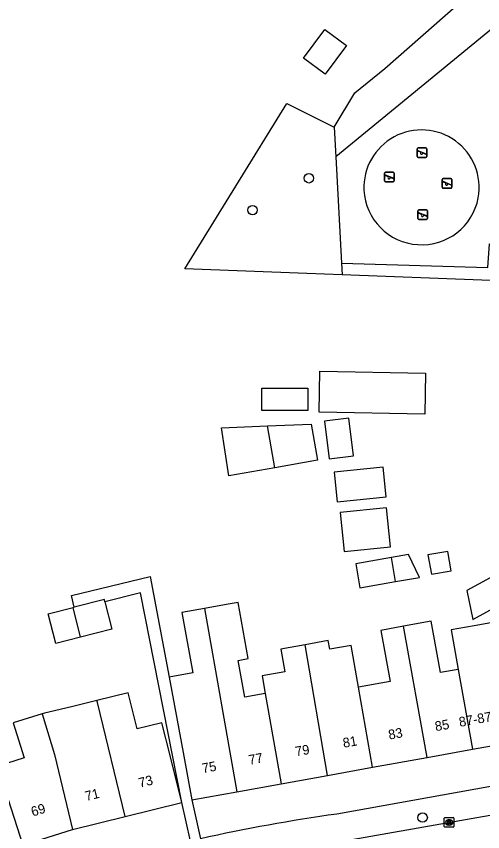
# Model space of a CAD drawing. Extents: x 160158 to 160921, y 381517 to 382041.
# Drawn here: x 160425.2 to 160473.6, y 381721.4 to 381806 of the extents above; entities that cross this region are included whole.
import ezdxf

# ---------------------------------------------------------------- set-up
doc = ezdxf.new("R2010")
doc.units = 0
for name, color, linetype in [('IMGEO_Boom', 7, 'Continuous'), ('IMGEO_Groenvoorziening', 7, 'Continuous'), ('IMGEO_Kolk', 7, 'Continuous'), ('IMGEO_Pand', 7, 'Continuous'), ('IMGEO_Pand_nummerreeks', 7, 'Continuous'), ('IMGEO_Rijbaan_lokaal_open', 7, 'Continuous'), ('IMGEO_Speelvoorziening', 7, 'Continuous'), ('IMGEO_Voetpad_open', 7, 'Continuous')]:
    doc.layers.add(name, color=color, linetype=linetype)

msp = doc.modelspace()

# ---------------------------------------------------------------- linework, layer by layer
at = {"layer": 'IMGEO_Boom'}
for centre in [(160455.579, 381789.21), (160449.734, 381785.912), (160467.376, 381722.867)]:
    msp.add_circle(centre, 0.489, dxfattribs=at)
at = {"layer": 'IMGEO_Groenvoorziening'}
for points in [[(160458.209, 381794.524), (160460.339, 381798.072), (160463.455, 381800.599), (160473.68, 381809.649), (160478.409, 381814.815)], [(160482.021, 381811.85), (160479.918, 381809.167), (160458.371, 381791.432)], [(160459.011, 381779.182), (160455.366, 381779.322), (160442.688, 381779.806), (160453.283, 381796.984), (160458.209, 381794.524)], [(160458.209, 381794.524), (160458.371, 381791.432)], [(160458.371, 381791.432), (160458.948, 381780.395)], [(160458.948, 381780.395), (160474.146, 381779.946), (160474.316, 381782.426), (160495.817, 381780.983)], [(160458.948, 381780.395), (160459.011, 381779.182)], [(160495.695, 381777.781), (160473.521, 381778.628), (160459.011, 381779.182)]]:
    msp.add_lwpolyline(points, dxfattribs=at)
for centre, radius, start, end in [((160467.262, 381788.252), 5.98, 349.80072, 182.53906), ((160467.265, 381788.296), 5.985, 182.96158, 349.37821)]:
    msp.add_arc(centre, radius, start, end, dxfattribs=at)
at = {"layer": 'IMGEO_Kolk'}
for p, q in [((160469.619, 381721.936), (160469.619, 381722.788)), ((160469.694, 381722.862), (160470.546, 381722.862)), ((160470.107, 381722.642), (160470.132, 381722.642)), ((160470.62, 381722.788), (160470.62, 381721.936)), ((160470.546, 381721.862), (160469.694, 381721.862)), ((160470.13, 381722.082), (160470.105, 381722.082))]:
    msp.add_line(p, q, dxfattribs=at)
for points in [[(160469.619, 381721.936), (160469.619, 381722.788)], [(160469.694, 381722.862), (160470.546, 381722.862)], [(160469.94, 381722.562), (160470.063, 381722.562), (160470.063, 381722.411), (160470.193, 381722.562), (160470.357, 381722.562), (160470.211, 381722.411), (160470.364, 381722.162), (160470.212, 381722.162), (160470.127, 381722.326), (160470.063, 381722.259), (160470.063, 381722.162), (160469.94, 381722.162), (160469.94, 381722.562)], [(160470.62, 381722.788), (160470.62, 381721.936)], [(160470.546, 381721.862), (160469.694, 381721.862)]]:
    msp.add_lwpolyline(points, dxfattribs=at)
for centre, start, end in [((160469.696, 381722.786), 91.55205, 178.44795), ((160469.696, 381722.786), 91.55205, 178.44795), ((160470.544, 381722.786), 1.55205, 88.44795), ((160470.544, 381722.786), 1.55205, 88.44795), ((160469.696, 381721.938), 181.55205, 268.44795), ((160469.696, 381721.938), 181.55205, 268.44795), ((160470.544, 381721.938), 271.55205, 358.44795), ((160470.544, 381721.938), 271.55205, 358.44795)]:
    msp.add_arc(centre, 0.0765, start, end, dxfattribs=at)
for centre, major_axis, ratio, start_param, end_param in [((160470.106, 381722.362), (-0.387, 0.002), 0.722429, 4.712389, 7.853982), ((160470.131, 381722.362), (-0.39, 0.002), 0.717154, 1.570796, 4.712389)]:
    msp.add_ellipse(centre, major_axis=major_axis, ratio=ratio, start_param=start_param, end_param=end_param, dxfattribs=at)
at = {"layer": 'IMGEO_Pand'}
for points in [[(160457.222, 381804.671), (160459.482, 381802.99), (160457.263, 381800.007), (160455.003, 381801.688), (160457.222, 381804.671)], [(160456.723, 381769.193), (160467.67, 381768.98), (160467.586, 381764.727), (160456.639, 381764.941), (160456.723, 381769.193)], [(160450.684, 381767.436), (160455.461, 381767.436), (160455.461, 381765.129), (160450.684, 381765.129), (160450.684, 381767.436)], [(160451.296, 381763.518), (160455.802, 381763.698), (160456.483, 381759.963), (160452.039, 381759.176)], [(160457.689, 381760.087), (160460.216, 381760.409), (160459.717, 381764.331), (160457.19, 381764.009), (160457.689, 381760.087)], [(160452.039, 381759.176), (160447.279, 381758.333), (160446.516, 381763.327), (160451.296, 381763.518)], [(160452.039, 381759.176), (160451.296, 381763.518)], [(160458.49, 381755.634), (160463.575, 381756.136), (160463.27, 381759.227), (160458.185, 381758.725), (160458.49, 381755.634)], [(160459.219, 381750.492), (160464.026, 381750.966), (160463.627, 381755.014), (160458.82, 381754.539), (160459.219, 381750.492)], [(160464.575, 381747.357), (160467.04, 381747.792), (160465.923, 381750.166), (160464.135, 381749.85)], [(160468.284, 381748.111), (160470.334, 381748.481), (160469.973, 381750.485), (160467.923, 381750.115), (160468.284, 381748.111)], [(160464.135, 381749.85), (160460.437, 381749.198), (160460.876, 381746.705), (160464.575, 381747.357)], [(160464.575, 381747.357), (160464.135, 381749.85)], [(160471.969, 381746.44), (160472.579, 381743.425), (160476.938, 381745.793), (160474.382, 381747.751), (160471.969, 381746.44)], [(160434.412, 381745.253), (160434.351, 381745.492), (160431.229, 381744.692)], [(160434.412, 381745.253), (160435.139, 381742.423), (160431.894, 381741.59)], [(160451.034, 381735.746), (160448.923, 381735.366), (160448.236, 381739.18), (160449.275, 381739.367), (160448.226, 381745.193), (160447.187, 381745.006), (160444.726, 381744.563)], [(160431.894, 381741.59), (160429.304, 381740.925), (160428.516, 381743.995), (160431.106, 381744.66)], [(160431.106, 381744.66), (160431.229, 381744.692)], [(160431.894, 381741.59), (160431.106, 381744.66)], [(160444.726, 381744.563), (160442.398, 381744.144), (160443.525, 381737.883), (160441.064, 381737.44)], [(160444.726, 381744.563), (160448.085, 381725.541)], [(160465.393, 381742.715), (160463.042, 381742.292), (160464, 381736.971), (160460.725, 381736.382)], [(160471.074, 381738.24), (160469.223, 381737.907), (160468.265, 381743.232), (160465.393, 381742.715)], [(160467.851, 381729.099), (160465.393, 381742.715)], [(160475.027, 381743.189), (160474.825, 381743.153), (160472.71, 381742.772), (160470.335, 381742.344), (160471.074, 381738.24)], [(160460.725, 381736.382), (160459.961, 381740.724), (160457.747, 381740.334), (160457.585, 381741.234), (160455.186, 381740.802)], [(160455.186, 381740.802), (160452.655, 381740.346), (160453.081, 381737.983), (160450.714, 381737.568), (160451.034, 381735.746)], [(160457.509, 381727.237), (160455.186, 381740.802)], [(160471.074, 381738.24), (160472.561, 381729.947)], [(160441.064, 381737.44), (160441.896, 381732.975), (160442.536, 381729.622), (160443.422, 381724.701)], [(160442.382, 381724.436), (160441.175, 381729.289), (160440.325, 381732.707), (160437.753, 381732.067), (160436.82, 381735.818), (160433.583, 381735.013)], [(160462.186, 381728.079), (160460.725, 381736.382)], [(160433.583, 381735.013), (160430.954, 381734.36), (160428.133, 381733.705), (160427.914, 381733.636)], [(160436.504, 381722.975), (160433.633, 381734.795), (160433.583, 381735.013)], [(160451.034, 381735.746), (160452.68, 381726.368)], [(160427.914, 381733.636), (160424.9, 381732.683), (160426.048, 381729.052), (160423.295, 381728.182), (160424.38, 381724.749), (160425.888, 381719.981), (160431.065, 381721.617)], [(160427.914, 381733.636), (160429.178, 381729.423), (160431.065, 381721.617)], [(160472.561, 381729.947), (160477.25, 381730.792)], [(160467.851, 381729.099), (160472.561, 381729.947)], [(160462.186, 381728.079), (160467.851, 381729.099)], [(160457.509, 381727.237), (160462.186, 381728.079)], [(160452.68, 381726.368), (160457.509, 381727.237)], [(160448.085, 381725.541), (160452.68, 381726.368)], [(160443.422, 381724.701), (160448.085, 381725.541)], [(160436.504, 381722.975), (160442.382, 381724.436)], [(160431.065, 381721.617), (160436.504, 381722.975)]]:
    msp.add_lwpolyline(points, dxfattribs=at)
at = {"layer": 'IMGEO_Rijbaan_lokaal_open'}
msp.add_lwpolyline([(160458.857, 381720.382), (160484.206, 381724.841), (160488.392, 381725.543), (160490.606, 381725.966), (160494.319, 381726.608), (160495.077, 381726.768)], dxfattribs=at)
at = {"layer": 'IMGEO_Speelvoorziening'}
for p, q in [((160466.81, 381791.48), (160466.81, 381792.28)), ((160466.81, 381792.28), (160466.81, 381791.48)), ((160467.193, 381791.908), (160466.854, 381792.045)), ((160466.879, 381792.105), (160467.755, 381791.752)), ((160466.91, 381792.38), (160467.7, 381792.38)), ((160467.7, 381792.38), (160466.91, 381792.38)), ((160467.731, 381791.692), (160467.391, 381791.829)), ((160467.8, 381792.28), (160467.8, 381791.48)), ((160467.8, 381791.48), (160467.8, 381792.28)), ((160467.7, 381791.38), (160466.91, 381791.38)), ((160466.91, 381791.38), (160467.7, 381791.38)), ((160463.43, 381788.94), (160463.43, 381789.74)), ((160463.43, 381789.74), (160463.43, 381788.94)), ((160463.813, 381789.368), (160463.474, 381789.505)), ((160463.499, 381789.565), (160464.375, 381789.212)), ((160463.53, 381789.84), (160464.32, 381789.84)), ((160464.32, 381789.84), (160463.53, 381789.84)), ((160464.351, 381789.152), (160464.011, 381789.289)), ((160464.42, 381789.74), (160464.42, 381788.94)), ((160464.42, 381788.94), (160464.42, 381789.74)), ((160469.504, 381789.176), (160470.294, 381789.176)), ((160470.294, 381789.176), (160469.504, 381789.176)), ((160464.32, 381788.84), (160463.53, 381788.84)), ((160463.53, 381788.84), (160464.32, 381788.84)), ((160469.404, 381788.276), (160469.404, 381789.076)), ((160469.404, 381789.076), (160469.404, 381788.276)), ((160469.787, 381788.704), (160469.448, 381788.841)), ((160469.473, 381788.901), (160470.349, 381788.548)), ((160470.325, 381788.488), (160469.985, 381788.625)), ((160470.394, 381789.076), (160470.394, 381788.276)), ((160470.394, 381788.276), (160470.394, 381789.076)), ((160470.294, 381788.176), (160469.504, 381788.176)), ((160469.504, 381788.176), (160470.294, 381788.176)), ((160466.889, 381785.037), (160466.889, 381785.837)), ((160466.889, 381785.837), (160466.889, 381785.037)), ((160466.989, 381785.937), (160467.779, 381785.937)), ((160467.779, 381785.937), (160466.989, 381785.937)), ((160467.879, 381785.837), (160467.879, 381785.037)), ((160467.879, 381785.037), (160467.879, 381785.837)), ((160467.272, 381785.465), (160466.933, 381785.602)), ((160466.958, 381785.662), (160467.834, 381785.309)), ((160467.779, 381784.937), (160466.989, 381784.937)), ((160466.989, 381784.937), (160467.779, 381784.937)), ((160467.81, 381785.249), (160467.47, 381785.386))]:
    msp.add_line(p, q, dxfattribs=at)
for centre, radius, start, end in [((160466.91, 381792.28), 0.1, 90, 180), ((160466.91, 381792.28), 0.1, 90, 180), ((160466.867, 381792.075), 0.0327, 68.07798, 248.07798), ((160467.272, 381791.818), 0.12, 130.99278, 5.16318), ((160467.7, 381792.28), 0.1, 0, 90), ((160467.7, 381792.28), 0.1, 360, 90), ((160467.743, 381791.722), 0.0327, 248.07798, 68.07798), ((160466.91, 381791.48), 0.1, 180, 270), ((160466.91, 381791.48), 0.1, 180, 270), ((160467.7, 381791.48), 0.1, 270, 0), ((160467.7, 381791.48), 0.1, 270, 0), ((160463.53, 381789.74), 0.1, 90, 180), ((160463.53, 381789.74), 0.1, 90, 180), ((160463.487, 381789.535), 0.0327, 68.07798, 248.07798), ((160463.892, 381789.278), 0.12, 130.99278, 5.16318), ((160464.32, 381789.74), 0.1, 0, 90), ((160464.32, 381789.74), 0.1, 360, 90), ((160464.363, 381789.182), 0.0327, 248.07798, 68.07798), ((160469.504, 381789.076), 0.1, 90, 180), ((160469.504, 381789.076), 0.1, 90, 180), ((160470.294, 381789.076), 0.1, 0, 90), ((160470.294, 381789.076), 0.1, 360, 90), ((160463.53, 381788.94), 0.1, 180, 270), ((160463.53, 381788.94), 0.1, 180, 270), ((160464.32, 381788.94), 0.1, 270, 0), ((160464.32, 381788.94), 0.1, 270, 0), ((160469.504, 381788.276), 0.1, 180, 270), ((160469.504, 381788.276), 0.1, 180, 270), ((160469.461, 381788.871), 0.0327, 68.07798, 248.07798), ((160469.866, 381788.614), 0.12, 130.99278, 5.16318), ((160470.294, 381788.276), 0.1, 270, 0), ((160470.294, 381788.276), 0.1, 270, 0), ((160470.337, 381788.518), 0.0327, 248.07798, 68.07798), ((160466.989, 381785.837), 0.1, 90, 180), ((160466.989, 381785.837), 0.1, 90, 180), ((160467.779, 381785.837), 0.1, 0, 90), ((160467.779, 381785.837), 0.1, 360, 90), ((160466.989, 381785.037), 0.1, 180, 270), ((160466.989, 381785.037), 0.1, 180, 270), ((160466.946, 381785.632), 0.0327, 68.07798, 248.07798), ((160467.351, 381785.375), 0.12, 130.99278, 5.16318), ((160467.779, 381785.037), 0.1, 270, 0), ((160467.779, 381785.037), 0.1, 270, 0), ((160467.822, 381785.279), 0.0327, 248.07798, 68.07798)]:
    msp.add_arc(centre, radius, start, end, dxfattribs=at)
at = {"layer": 'IMGEO_Voetpad_open'}
for points in [[(160431.229, 381744.692), (160430.936, 381745.898), (160439.118, 381747.885), (160441.064, 381737.44)], [(160442.382, 381724.436), (160438.098, 381746.2), (160434.412, 381745.253)], [(160493.473, 381729.503), (160458.476, 381723.221)], [(160443.305, 381720.427), (160442.382, 381724.436)], [(160443.422, 381724.701), (160444.327, 381720.659)]]:
    msp.add_lwpolyline(points, dxfattribs=at)
msp.add_arc((160482.422, 381550.627), 174.247, 97.89878, 102.62823, dxfattribs=at)

# ---------------------------------------------------------------- texts
at = {"layer": 'IMGEO_Pand_nummerreeks'}
for s, rotation, p in [('87-87A', 10.21584, (160471.232, 381732.268)), ('85', 10.20649, (160468.742, 381731.82)), ('83', 10.20649, (160463.909, 381730.95)), ('81', 10.20438, (160459.187, 381730.099)), ('79', 10.20438, (160454.244, 381729.209)), ('77', 10.20438, (160449.411, 381728.339)), ('75', 10.20649, (160444.578, 381727.469)), ('73', 13.96309, (160438.033, 381725.952)), ('71', 14.01091, (160432.483, 381724.569)), ('69', 17.53967, (160426.929, 381722.953))]:
    msp.add_text(s, height=1, rotation=rotation, dxfattribs=at).set_placement(p)

doc.saveas('drawing.dxf')
